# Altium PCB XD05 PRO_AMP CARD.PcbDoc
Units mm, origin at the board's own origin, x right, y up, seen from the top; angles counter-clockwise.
Board outline 39.9 x 32.4 mm, 4 copper layers (Top Layer, Signal Layer 1, Signal Layer 2, Bottom Layer), stack 1.58 mm thick; 39 components, 719 nets, 142 pads, 70 vias.
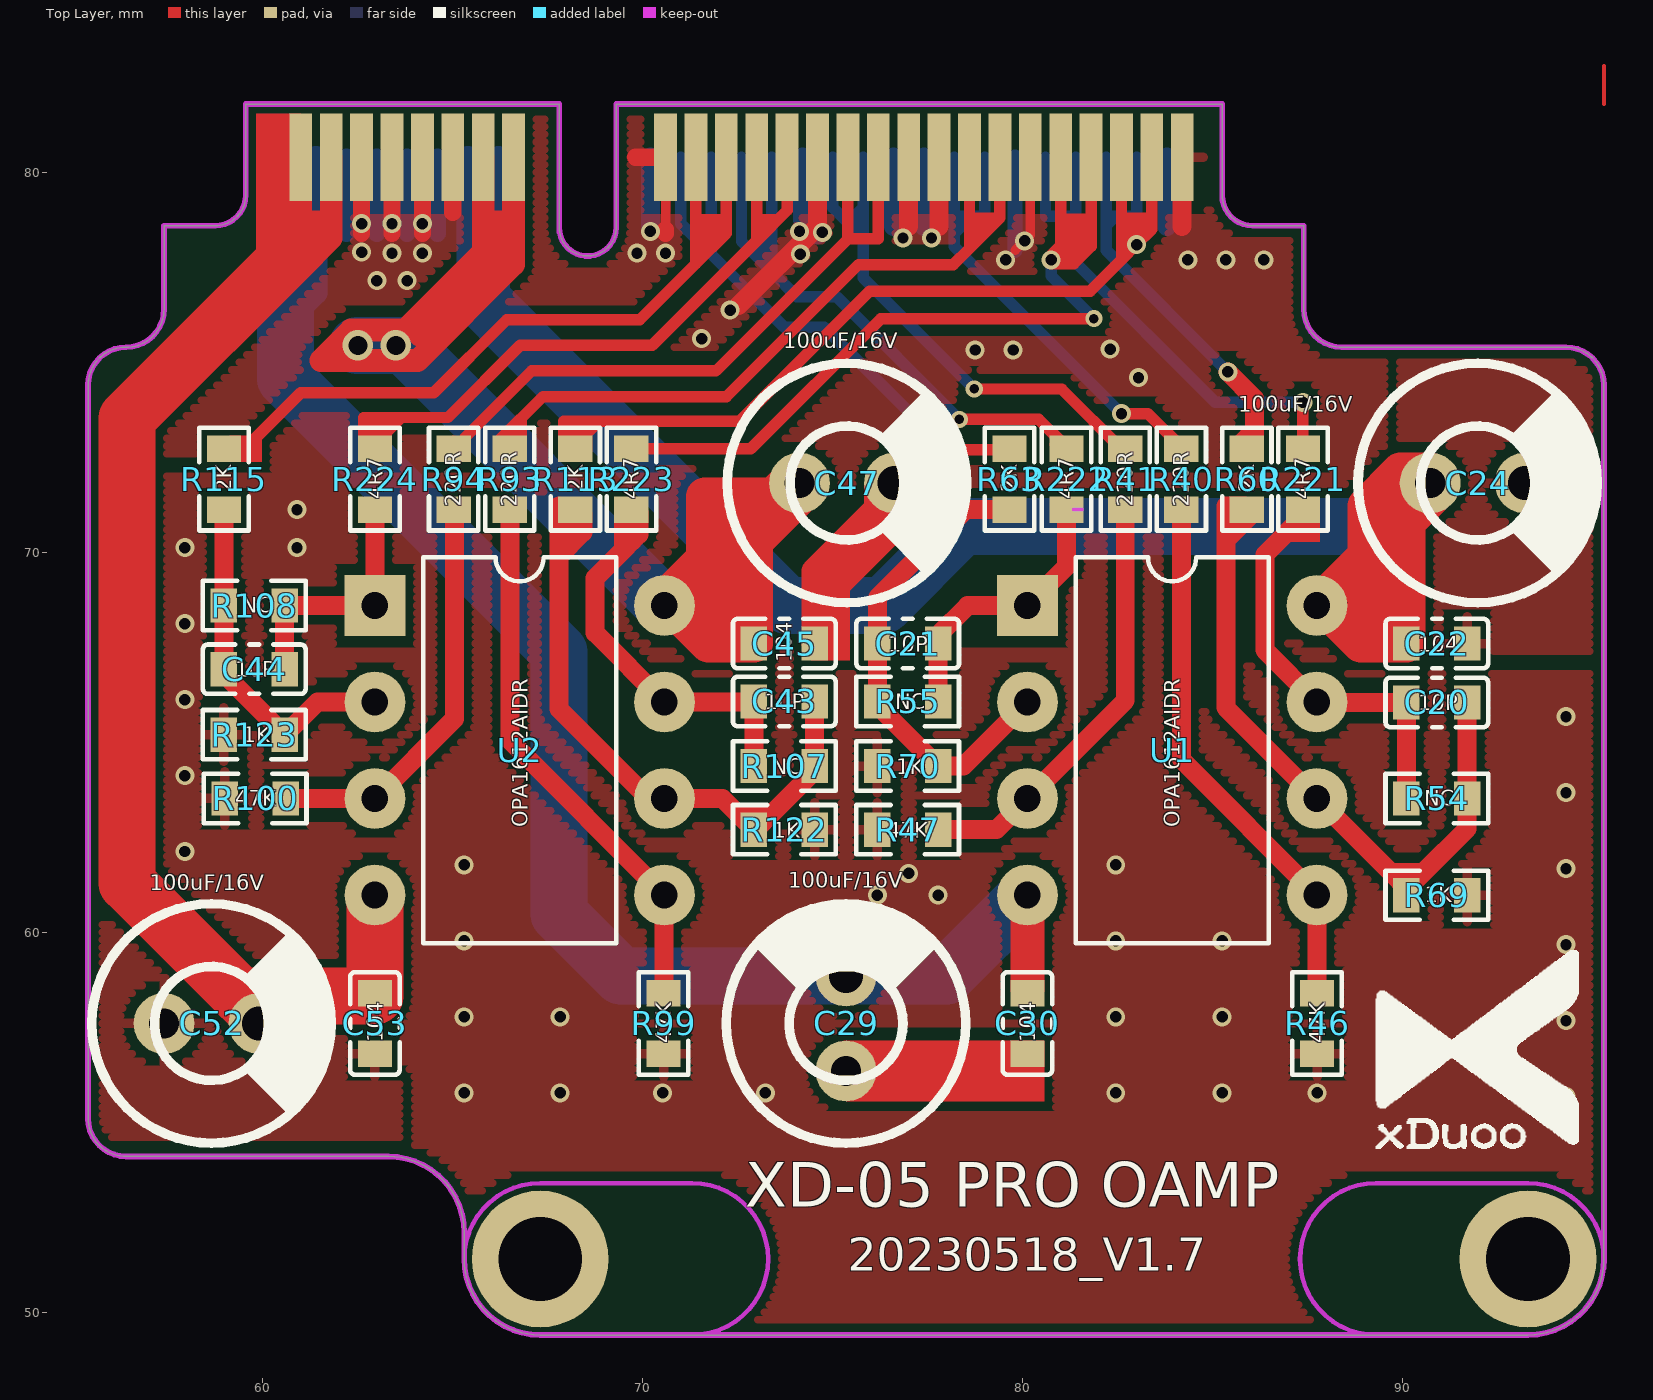
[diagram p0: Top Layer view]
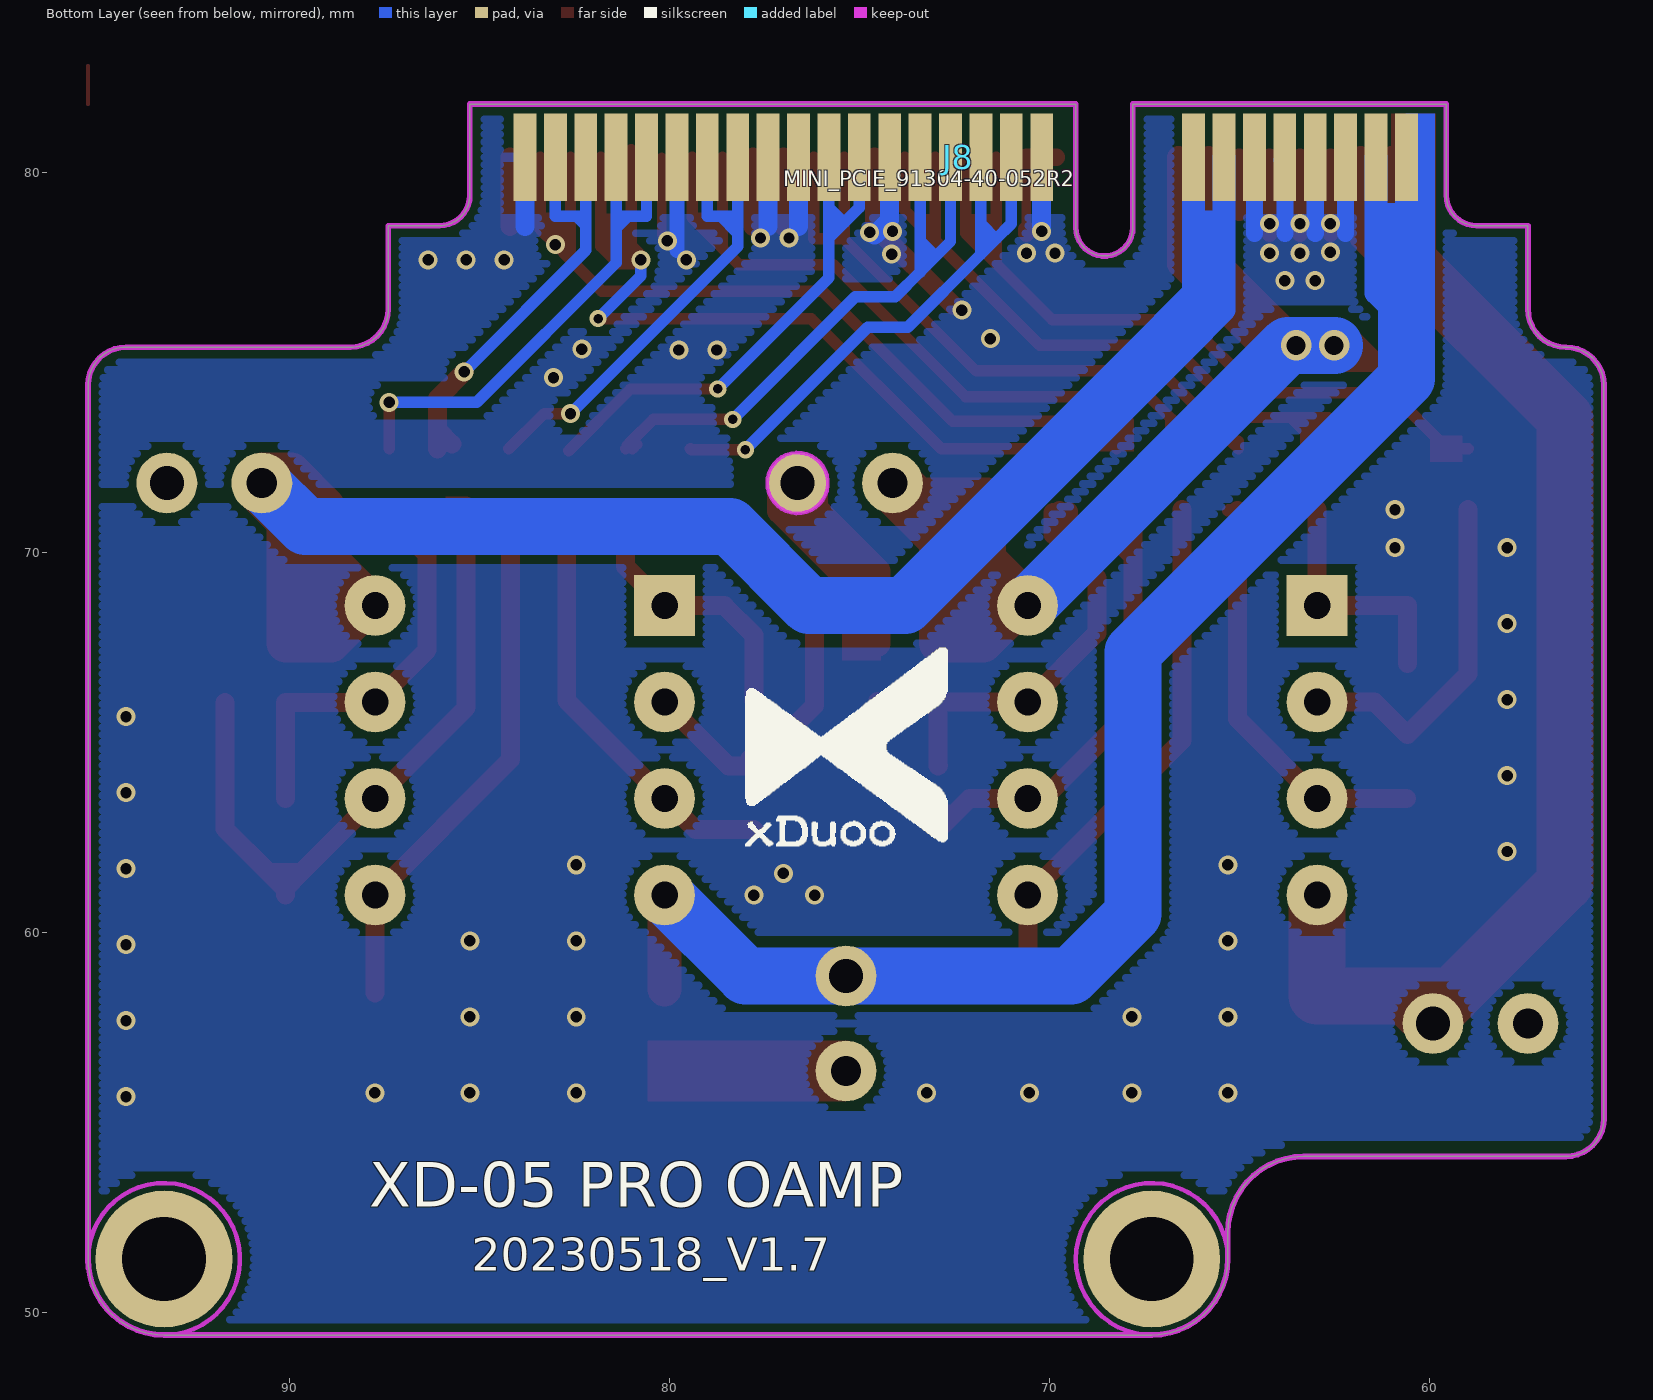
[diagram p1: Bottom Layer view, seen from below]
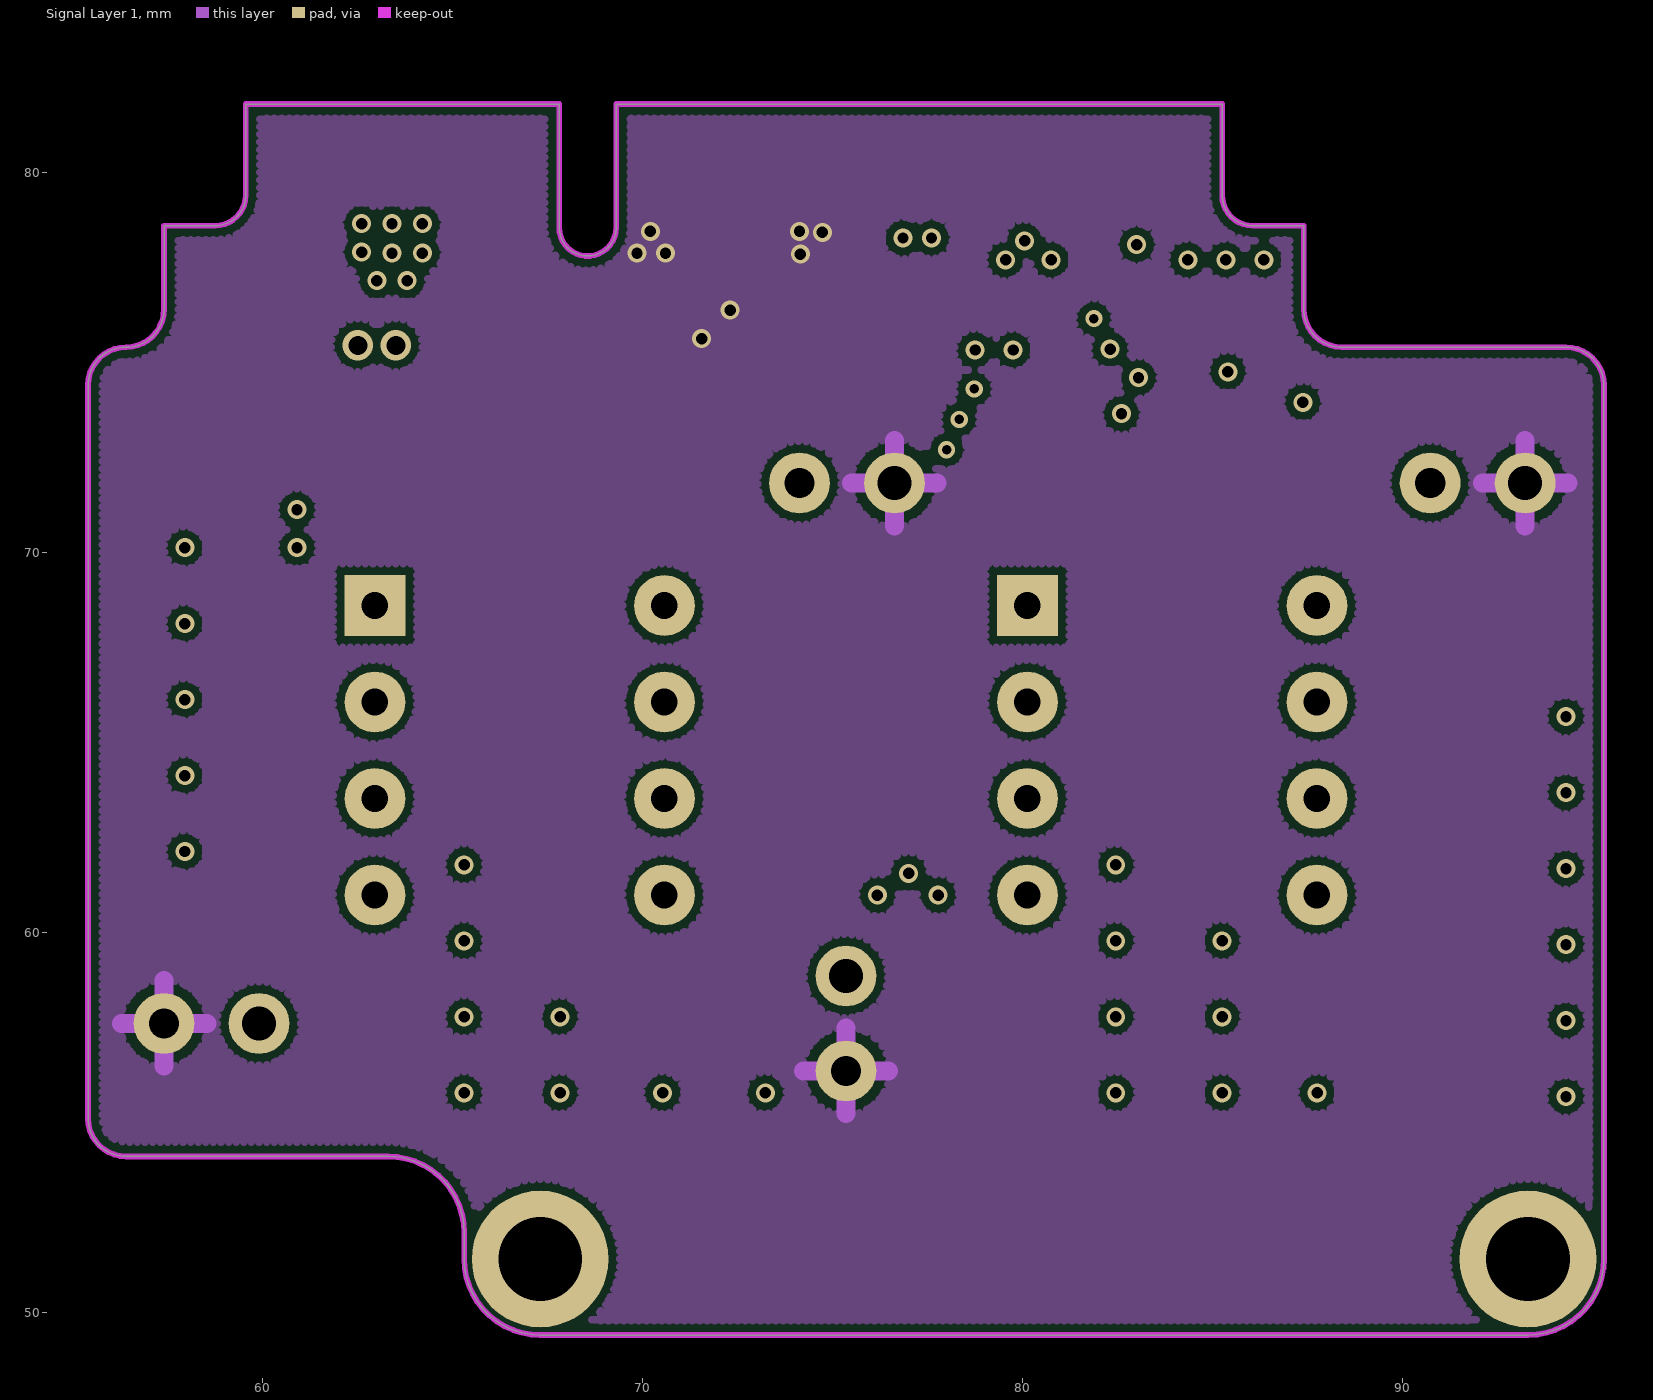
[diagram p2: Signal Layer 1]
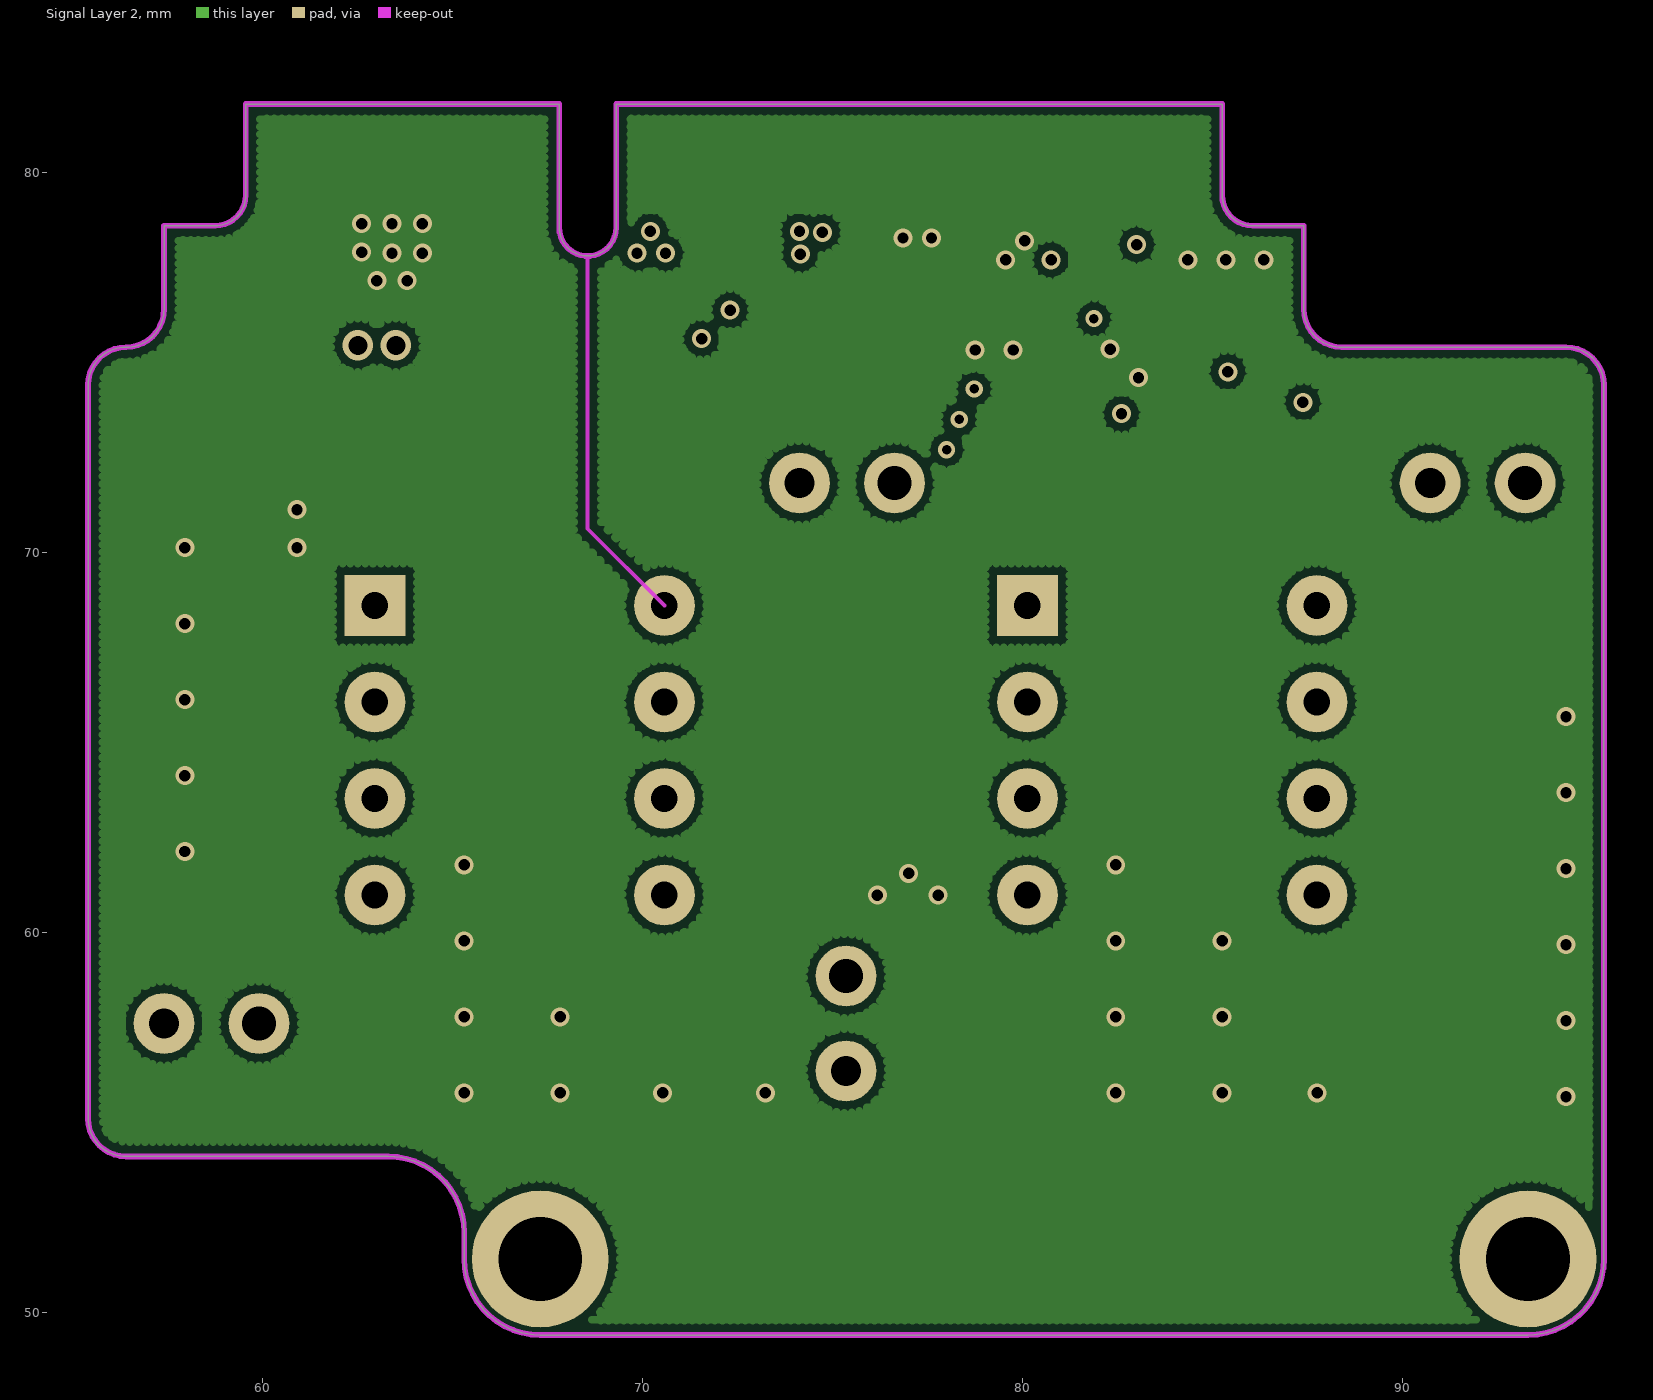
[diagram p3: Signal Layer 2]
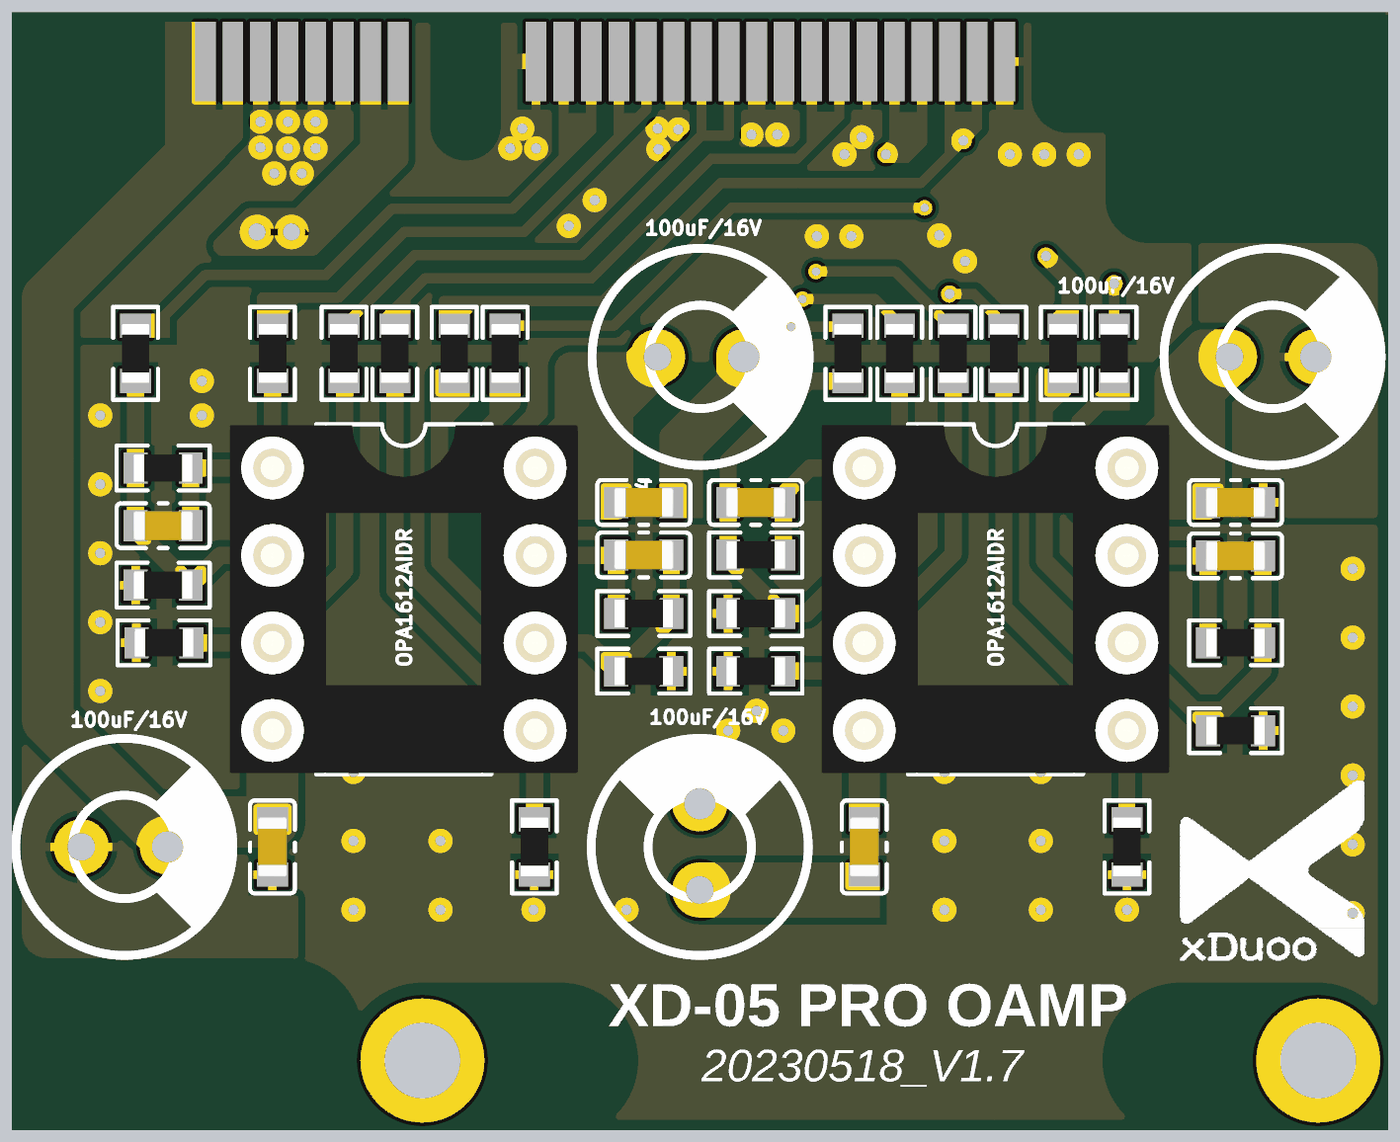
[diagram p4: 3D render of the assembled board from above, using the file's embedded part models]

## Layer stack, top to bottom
Top Solder: solder mask 0.01, Solder Resist, Dk 3.5
Top Layer: signal copper 0.035
Dielectric 1: core 0.48, FR-4, Dk 4.2
Signal Layer 1: signal copper 0.035
Dielectric 3: prepreg 0.48, Dk 4.2
Signal Layer 2: signal copper 0.035
Dielectric 2: core 0.48, Dk 4.2
Bottom Layer: signal copper 0.035
Bottom Solder: solder mask 0.01, Solder Resist, Dk 3.5

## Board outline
56.4,54.1 63.3,54.1 cw(c63.3,52.1) 65.3,52.1 65.3,51.4 ccw(c67.3,51.4) 67.3,49.4 93.3,49.4 ccw(c93.3,51.4) 95.3,51.4 95.3,74.4 ccw(c94.3,74.4) 94.3,75.4 88.4,75.4 cw(c88.4,76.4) 87.4,76.4 87.4,78.6 86.05,78.6 cw(c86.05,79.4) 85.25,79.4 85.25,81.8 69.3,81.8 69.3,78.55 cw(c68.55,78.55) 67.8,78.55 67.8,81.8 59.55,81.8 59.55,79.4 cw(c58.75,79.4) 58.75,78.6 57.4,78.6 57.4,76.4 cw(c56.4,76.4) 56.4,75.4 ccw(c56.4,74.4) 55.4,74.4 55.4,55.1 ccw(c56.4,55.1)

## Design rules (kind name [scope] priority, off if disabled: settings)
Clearance [All] p1: gap=0.2 ignorepadtopadclearanceinfootprint=FALSE except(0: Arc-Hole Track-Hole SMDPad-Hole THPad-Hole Via-Hole Fill-Hole Poly-Hole Region-Hole Text-Hole)
PlaneConnect [All] p1: planeconnectstyle=Relief reliefexpansion=0.508 reliefentries=4 reliefconductorwidth=0.25 reliefairgap=0.254
PolygonConnect PolygonConnect_1 [All vs IsVia] p1: connectstyle=Direct reliefconductorwidth=0.254 reliefentries=4 polygonreliefangle="90 Angle" airgapwidth=0.254
PolygonConnect [All] p2: connectstyle=Relief reliefconductorwidth=0.25 reliefentries=4 polygonreliefangle="90 Angle" airgapwidth=0.254
RoutingVias [All] p1: holewidth=0.25 width=0.45 viastyle="Through Hole" minholewidth=0.25 minwidth=0.45 maxholewidth=0.25 maxwidth=0.45
SolderMaskExpansion [All] p1: expansion=0.102
Width [All] p1: maxlimit=10 minlimit=0.15 preferedwidth=0.15
29 further rules are at their usual default settings.

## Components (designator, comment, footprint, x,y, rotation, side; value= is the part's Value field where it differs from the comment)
C20 "10P" C0603 91.7,66.05 r180 top
C21 "10P" C0603 76.175,67.6 r0 top
C22 "104" C0603 90.1,67.6 r0 top
C24 "100uF/16V" C6.5 90.725,71.825 r0 top
C29 "100uF/16V" C6.5 75.35,56.35 r90 top locked
C30 "104" C0603 80.125,58.4 r270 top
C43 "10P" C0603 74.525,66.075 r180 top
C44 "10P" C0603 58.975,66.925 r0 top
C45 "104" C0603 72.925,67.6 r0 top
C47 "100uF/16V" C6.5 74.125,71.825 r0 top
C52 "100uF/16V" C6.5 57.4,57.6 r0 top
C53 "104" C0603 62.95,58.4 r270 top
J8 "MINI_PCIE_91304-40-052R2" MINI_PCIE_91304-40-052R2_PCB 72.4,81.8 r0 bottom locked
R40 "220R" R0603 84.175,72.725 r270 top
R41 "220R" R0603 82.7,72.725 r270 top
R46 "47K" R0603 87.75,58.4 r270 top
R47 "47K" R0603 77.775,62.7 r180 top
R54 "NC" R0603 91.7,63.525 r180 top
R55 "NC" R0603 76.175,66.075 r0 top
R60 "2K" R0603 85.9,71.125 r90 top
R63 "2K" R0603 79.65,71.125 r90 top
R69 "1K" R0603 90.1,60.975 r0 top
R70 "1K" R0603 77.775,64.375 r180 top
R93 "220R" R0603 66.5,72.725 r270 top
R94 "220R" R0603 65.025,72.725 r270 top
R99 "47K" R0603 70.55,58.4 r270 top
R100 "47K" R0603 60.6,63.525 r180 top
R107 "NC" R0603 74.525,64.375 r180 top
R108 "NC" R0603 58.975,68.6 r0 top
R113 "2K" R0603 68.225,71.125 r90 top
R115 "2K" R0603 58.975,71.125 r90 top
R122 "1K" R0603 72.925,62.7 r0 top
R123 "1K" R0603 60.575,65.2 r180 top
R221 "4R7" R0603 87.375,71.125 r90 top
R222 "4R7" R0603 81.15,71.125 r90 top
R223 "4R7" R0603 69.7,71.125 r90 top
R224 "4R7" R0603 62.95,71.125 r90 top
U1 "OPA1612AIDR" DIP8 80.125,68.6 r0 top locked
U2 "OPA1612AIDR" DIP8 62.95,68.6 r0 top locked

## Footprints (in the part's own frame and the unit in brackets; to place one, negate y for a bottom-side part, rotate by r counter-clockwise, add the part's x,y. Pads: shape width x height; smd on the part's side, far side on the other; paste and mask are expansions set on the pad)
C6.5 [mm]
  round 1.6 hole 0.8: 1(0,0)
  round 1.6 hole 0.9: 2(2.5,0)
  silkscreen extent -1.9,-3.15 4.4,3.15, body extent -1.94,-3.2 4.44,3.2, height 2.5
C0603 [mm]
  rect 0.7x0.9 smd: 1(0,0) 2(1.6,0)
  silkscreen extent -0.55,-0.65 2.15,0.65, body extent -0.07,-0.44 1.68,0.44, height 0.92
DIP8 [mm]
  rect 1.6x1.6 hole 0.7: 1(0,0)
  round 1.6 hole 0.7: 2(0,-2.54) 3(0,-5.08) 4(0,-7.62) 5(7.62,-7.62) 6(7.62,-5.08) 7(7.62,-2.54) 8(7.62,0)
  silkscreen extent 1.27,-8.89 6.35,1.27, body extent -1.24,-8.86 8.86,1.24, height 4.6
MINI_PCIE_91304-40-052R2_PCB [mm]
  rect 0.6x2.3 smd: 1(-11.8,1.4) 3(-11,1.4) 5(-10.2,1.4) 7(-9.4,1.4) 9(-8.6,1.4) 11(-7.8,1.4) 13(-7,1.4) 15(-6.2,1.4) 17(-2.2,1.4) 19(-1.4,1.4) 21(-0.6,1.4) 23(0.2,1.4) 25(1,1.4) 27(1.8,1.4) 29(2.6,1.4) 31(3.4,1.4) 33(4.2,1.4) 35(5,1.4) 37(5.8,1.4) 39(6.6,1.4) 41(7.4,1.4) 43(8.2,1.4) 45(9,1.4) 47(9.8,1.4) 49(10.6,1.4) 51(11.4,1.4)
  rect 0.6x2.3 smd far side: 2(-11.4,1.4) 4(-10.6,1.4) 6(-9.8,1.4) 8(-9,1.4) 10(-8.2,1.4) 12(-7.4,1.4) 14(-6.6,1.4) 16(-5.8,1.4) 18(-1.8,1.4) 20(-1,1.4) 22(-0.2,1.4) 24(0.6,1.4) 26(1.4,1.4) 28(2.2,1.4) 30(3,1.4) 32(3.8,1.4) 34(4.6,1.4) 36(5.4,1.4) 38(6.2,1.4) 40(7,1.4) 42(7.8,1.4) 44(8.6,1.4) 46(9.4,1.4) 48(10.2,1.4) 50(11,1.4) 52(11.8,1.4)
  Keep-Out Layer lines w0.15: -15,3.2 -13.65,3.2 cw(c-13.65,2.4) -12.85,2.4 -12.85,0 -4.6,0 -4.6,3.25 cw(c-3.85,3.25) -3.1,3.25 -3.1,0 12.85,0 12.85,2.4 cw(c13.65,2.4) 13.65,3.2 15,3.2
R0603 [mm]
  rect 0.7x0.9 smd: 1(0,0) 2(1.6,0)
  silkscreen extent -0.55,-0.65 2.15,0.65, body extent -0.05,-0.4 1.65,0.4, height 0.55

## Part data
C20 C21 C22 C30 C43 C44 C45 C53: library part C
C24 C29 C47 C52: library part C+
R40 R41 R46 R47 R54 R55 R60 R63 R69 R70 R93 R94 R99 R100 R107 R108 R113 R115 R122 R123 R221 R222 R223 R224: library part R2
U1 U2: library part AMP

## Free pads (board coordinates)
  round 3.6 hole 2.2: 1(67.3,51.4) 1(93.3,51.4)

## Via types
v1: diameter 0.5, hole 0.3, Top Layer to Bottom Layer, 64 vias
v2: diameter 0.45, hole 0.25, Top Layer to Bottom Layer, 4 vias
v3: diameter 0.8, hole 0.5, Top Layer to Bottom Layer, 2 vias

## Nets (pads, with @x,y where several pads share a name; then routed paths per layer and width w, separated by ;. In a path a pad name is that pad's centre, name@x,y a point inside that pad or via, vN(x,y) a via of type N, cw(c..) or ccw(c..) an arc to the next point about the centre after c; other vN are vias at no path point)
3.5/4.4_SEL: 
3.5_EN: 
4.4_EN: 
4.4_IN_EN: 
4.4_L+: 
4.4_L-: 
4.4_LIN+: 
4.4_LIN-: 
4.4_LOUT+: 
4.4_LOUT-: 
4.4_OUT_EN: 
4.4_R+: 
4.4_R-: 
4.4_RIN+: 
4.4_RIN-: 
4.4_ROUT+: 
4.4_ROUT-: 
6.35/4.4_DET: 
+VCC: 
-VEE: 
A+8V: 
A+VCC: 
A-8V: 
A-VEE: 
AD_KEY1: 
AGND: J8.5 J8.6 J8.7 J8.8 J8.9 J8.10 J8.11 J8.12 J8.33 J8.34 J8.35 J8.36 J8.41 J8.42 J8.51 J8.52 R46.2 R47.2 R69.2 R70.2 R99.2 R100.2 R122.2 R123.2 | length 31.6
  Top Layer w0.25: 79.8,77.95 v1(80.05,78.2) 80.2,78.35 J8.42
  Top Layer w0.45: 62.6,78.4 J8.6 ; 63.4,78.4 J8.8 ; 64.2,78.4 v1(64.2,78.65) J8.10 ; 65,78.95 J8.12
  Top Layer w0.5: 77,78.575 J8.34 ; 77.8,78.575 J8.36 ; 84.2,78.575 J8.52
  Bottom Layer w0.4: 79.8,77.95 J8.41
  Bottom Layer w0.45: 62.2,78.4 J8.5 ; 63,78.4 J8.7 ; 63.8,78.4 J8.9 J8.9@63.875,80.325 ; 64.6,78.4 J8.11
  Bottom Layer w0.5: 76.6,78.575 J8.33 ; 77.4,78.575 J8.35 ; 83.8,78.575 J8.51
  other v1: 94.3,55.675 65.3,55.775 67.825,55.775 70.525,55.775 73.225,55.775 82.45,55.775 85.25,55.775 87.75,55.775 94.3,57.675 65.3,57.775 67.825,57.775 82.45,57.775 85.25,57.775 94.3,59.675 65.3,59.775 82.45,59.775 85.25,59.775 76.175,60.975 77.775,60.975 77,61.55 94.3,61.675 65.3,61.775 82.45,61.775 57.95,62.125 94.3,63.675 57.95,64.125 94.3,65.675 57.95,66.125 57.95,68.125 57.95,70.125 60.9,70.125 60.9,71.125 83.05,74.6 78.75,75.325 79.75,75.325 82.3,75.35 63,77.15 63.8,77.15 79.55,77.7 84.35,77.7 85.35,77.7 86.35,77.7 63.4,77.875 64.2,77.875 62.6,77.9 76.85,78.275 77.6,78.275 62.6,78.65 63.4,78.65
AGND_1: 
AGND_AP: C22.2 C24.2 C29.1 C30.2 C45.2 C47.2 C52.1 C53.2 J8.17 J8.18 J8.27 J8.28 | length 46.5
  Top Layer w0.25: 70.6,78.5 J8.18
  Top Layer w0.45: 69.811,80.4 J8.18 ; 70.6,78.4 70.6,78.5
  Top Layer w0.5: 72.525,76.5 74.6,78.575 J8.28 ; C47.2 C47.2@76.625,72.123
  Top Layer w0.7: C29.1@75.35,56.8 76.425,56.8 ; C29.1@75.775,56.15 76.425,56.8 ; C47.2 76.625,71.6 74.525,69.5 C45.2 75.1,67.6 75.1,69.125 77.075,71.1 C47.2@77.075,71.825 ; C30.2 76.425,56.8 ; C24.2@93.1,71.625 C24.2@93.1,71.825
  Signal Layer 1 w0.5: 56.275,57.6 C52.1 ; 57.4,58.725 C52.1 ; 57.4,56.475 C52.1 ; 58.525,57.6 C52.1 ; 74.225,56.35 C29.1 75.35,55.225 ; 75.35,57.475 C29.1 76.475,56.35 ; 75.5,71.825 C47.2 ; 76.625,70.7 C47.2 ; C47.2 77.75,71.825 ; 76.625,72.95 C47.2 ; 92.1,71.825 C24.2 ; 93.225,70.7 C24.2 ; C24.2 94.35,71.825 ; 93.225,72.95 C24.2
  Bottom Layer w0.5: v1@70.2,78.575 J8.17 ; J8.27 74.2,78.75 v1@74.6,78.35
  other v1: 71.55,75.625 72.3,76.375 74.15,77.85 69.85,77.875 70.6,77.875 74.725,78.425 70.2,78.45 74.125,78.45
AGND_L: 
AGND_LS: 
AGND_P: 
AGND_R: 
AGND_RS: 
AMP_L+: J8.37 J8.39 R40.1 | length 13.5
  Top Layer w0.3: v1(82.6,73.65) 83.3,73.65 R40.1@84.225,72.725
  Bottom Layer w0.3: J8.37 78.2,78.4 ; 78.225,78.85 78.65,78.85 ; J8.39 79,78.85 78.65,78.85 ; v1(82.6,73.65) 78.2,78.05 78.2,78.4 ; 78.2,78.4 78.65,78.85
AMP_L-: J8.29 J8.31 R41.1 | length 15.1
  Top Layer w0.3: v2(78.725,74.3) 81.025,74.3 R41.1@82.65,72.675
  Bottom Layer w0.3: J8.29 75,79.075 75.4,78.675 ; 75.625,78.625 75.625,78.775 ; J8.31 75.8,79.075 ; v2(78.725,74.3) 75.8,77.225 75.8,78.275 ; 75.4,78.675 75.8,78.275 ; 75.4,78.675 75.8,79.075 ; 75.8,78.275 75.8,79.075
AMP_PWR_EN: 
AMP_R+: J8.38 J8.40 R93.1 | length 20.8
  Top Layer w0.3: R93.1@66.225,72.95 67.375,74.1 72.205,74.1 75.68,77.575 78.175,77.575 78.6,78 ; J8.38 78.6,78 ; 78.625,78.8 79.4,78.8 ; 78.875,78.4 78.875,78.75 78.95,78.75 ; J8.40 79.4,78.8 ; 78.6,78 79.4,78.8
AMP_R-: J8.30 J8.32 R94.1 | length 17.8
  Top Layer w0.3: R94.1 R94.1@65.025,72.925 ; R94.1@65.125,72.825 67.075,74.775 71.925,74.775 75.4,78.25 J8.30 ; 75.4,78.25 76.2,78.25 J8.32
"AUDIO STREAM": 
AUX_L: 
AUX_L+: 
AUX_L-: 
AUX_LIN: 
AUX_LOUT: 
AUX_R: 
AUX_R+: 
AUX_R-: 
AUX_RIN: 
AUX_ROUT: 
AVCC_5V: 
BAT_DET: 
BD_SCL: 
BD_SDA: 
BOOST_A: 
BOOST_B: 
BOOT0: 
BT+3V3: 
BT_BCLK: 
BT_DATA: 
BT_DM: 
BT_DP: 
BT_LRCK: 
BT_MCLK: 
BT_OSC_SEL: 
BT_START: 
BT_UART_RX: 
BT_UART_TX: 
BT_VCC: 
C+3V3: 
CC1: 
CC2: 
CHG_DET: 
CHG_SW: 
CS_BCLK: 
CS_LRCK: 
CS_MCLK: 
CS_RST: 
CS_SDOUT: 
D+1V5: 
D+3V3: 
D+VCC: 
D-GND: 
DA+VCC: 
DA-VEE: 
DAC_L: 
DAC_L1+: 
DAC_L1-: 
DAC_L+: 
DAC_L-: 
DAC_LOUT: 
DAC_LOUT+: 
DAC_LOUT-: 
DAC_MCLK_SEL: 
DAC_PWR: 
DAC_PWR_EN: 
DAC_R: 
DAC_R1+: 
DAC_R1-: 
DAC_R+: 
DAC_R-: 
DAC_ROUT: 
DAC_ROUT+: 
DAC_ROUT-: 
DAC_RST: 
DAC_RST: 
DAC_SEL1: 
DAC_SEL2: 
DC_DET: 
DC_PWR_EN: 
DC_VCC: 
DGND: 
DIN: 
DM1: 
DM2: 
DM_IN: 
DOP_DET: 
DP1: 
DP2: 
DP_IN: 
DSD/PCM_MODE: 
DSD_CH: 
EXCLKI: 
EXCLKO: 
F+3V3: 
FS1: 
FS2: 
FS3: 
FS4: 
GW+1V2: 
GW+3V3: 
GW_SEL1: 
GW_SEL2: 
I2C_SCL: 
I2C_SDA: 
IBCLK: 
ILRCK: 
IOR3A: 
IOUT_LN: 
IOUT_LP: 
IOUT_RN: 
IOUT_RP: 
JTAG_TCK: 
JTAG_TDI: 
JTAG_TDO: 
JTAG_TMS: 
KEY: 
KEY_ON: 
L1+: 
L1-: 
L2+: 
L2-: 
L+: 
L+VCC: C22.1 C24.1 J8.13 J8.15 U1.8 | length 50.8
  Top Layer w1: C24.1@90.725,72.123 89.948,72.123 89.05,71.225 89.05,69.905 87.826,68.681 88.907,67.6 C22.1 90.1,70.8 C24.1@90.775,71.475
  Bottom Layer w0.6: J8.13 65.4,76.375 66.2,75.575 ; J8.15 66.2,76.85 67,76.05
  Bottom Layer w1.5: 66.225,76.175 73.8,68.6 76.325,68.6 78.4,70.675 89.575,70.675 C24.1
L-: 
L-VEE: C29.2 C30.1 J8.1 J8.3 U1.4 | length 43.8
  Top Layer w0.9: C30.1@80.125,58.5 U1.4@80.125,60.725
  Bottom Layer w0.6: 60.284,76.841 60.6,77.156 J8.1 ; 60.85,76.275 61.4,76.825 J8.3
  Bottom Layer w1.5: 60.6,77.156 60.6,74.573 67.8,67.373 67.8,60.475 69.425,58.85 C29.2 77.995,58.85 U1.4
L_CH: 
L_MUTE: 
L_VU_ADC: 
LI+: J8.43 J8.45 R221.2 | length 14.1
  Top Layer w0.3: R221.2 v1(87.375,73.95)
  Bottom Layer w0.3: J8.43 80.6,78.85 81.075,78.85 ; J8.45 81.4,78.85 ; 87.125,73.95 85.069,73.95 81.4,77.619 81.4,78.525 ; 81.075,78.85 81.4,78.85 ; 81.075,78.85 81.4,78.525 ; 81.4,78.525 81.4,78.85
LI-: J8.23 J8.25 R222.2 | length 17.7
  Top Layer w0.3: v2(78.331,73.5) 80.425,73.5 81,72.925 R222.2@81.113,72.812 ; R222.2@80.862,72.838 R222.2@80.975,72.725 ; R222.2@81.062,72.813 R222.2
  Bottom Layer w0.3: J8.23 72.6,78.181 73.4,77.381 ; 73,77.8 73.4,78.2 ; 73.225,77.7 73.225,77.9 ; 73.4,77.375 73.4,77.381 ; 73.4,78.9 73.4,78.25 ; J8.25 73.4,78.25 ; v2(78.331,73.5) 75.106,76.725 74.056,76.725 73.4,77.381 ; 73.4,77.381 73.4,78.2 ; 73.4,78.2 73.4,78.25 ; 73.4,78.2 73.4,78.25
LO+: J8.47 J8.49 R60.2 | length 12.5
  Top Layer w0.5: v1(85.4,74.75) 86.1,74.05 86.1,73.225 ; R60.2@85.725,72.85 86.1,73.225 ; R60.2@86.1,72.725 86.1,73.225
  Bottom Layer w0.3: J8.47 82.2,78.6 ; 82.225,78.85 82.45,78.85 ; J8.49 83,78.85 82.45,78.85 ; v1(85.4,74.75) 82.2,77.95 82.2,78.6 ; 82.2,78.6 82.45,78.85
LO-: J8.19 J8.21 R63.2 | length 16.3
  Top Layer w0.3: v2(78,72.7) 78.95,72.7 79.425,72.7 R63.2@79.45,72.725
  Bottom Layer w0.3: J8.19 71,78.65 71.4,78.25 ; 71.625,78.1 71.625,78.325 ; 71.8,78.9 71.8,78.65 ; J8.21 71.8,78.65 ; v2(78,72.7) 74.775,75.925 73.725,75.925 71.8,77.85 ; 71.4,78.25 71.8,78.65 ; 71.4,78.25 71.8,77.85 ; 71.8,77.85 71.8,78.65
M+3V3: 
MCLK: 
MCLK_1/2_SELA: 
MCLK_1/2_SELB: 
MCLK_SEL: 
MCLK_XCORE: 
MIC-AP: 
MIC-BIAS: 
MQA_LED: 
MUTE: 
MUTE_L: 
MUTE_R: 
MUTEING: 
MUTING: 
NetC1_2: 
NetC2_1: 
NetC3_1: 
NetC4_2: 
NetC5_1: 
NetC6_1: 
NetC7_2: 
NetC8_1: 
NetC9_2: 
NetC10_1: 
NetC11_1: 
NetC11_2: 
NetC16_1: 
NetC16_2: 
NetC17_1: 
NetC17_2: 
NetC18_1: 
NetC18_2: 
NetC20_1: C20.1 R54.1 R60.1 R69.1 U1.6 | length 19.6
  Top Layer w0.5: 85.35,71.225 85.35,70.325 ; R60.1@86.05,71.025 85.35,70.325 ; R69.1 90.1,61.165 89.69,61.575 ; R69.1@90.15,61.175 90.55,61.575 ; C20.1 91.7,62.725 90.55,61.575 ; 85.35,70.325 85.35,65.915 89.69,61.575 ; 89.69,61.575 90.55,61.575
NetC20_2: C20.2 R54.2 R221.1 U1.7 | length 11.2
  Top Layer w0.5: U1.7@87.51,66.05 C20.2 R54.2 ; R221.1@87.51,71.075 86.375,69.94 86.375,67.43 U1.7
NetC21_1: C21.1 R55.1 R63.1 R70.1 U1.2 | length 12.9
  Top Layer w0.35: U1.2@80.37,66.05 U1.2@80.38,66.06
  Top Layer w0.5: R70.1@77.875,64.575 77.775,64.475 R70.1 ; R63.1@79.7,71.125 78.5,71.125 76.175,68.8 C21.1 R55.1 76.175,65.975 R70.1 ; U1.2@80.11,66.075 U1.2 78.44,64.375 R70.1
NetC21_2: C21.2 R55.2 R222.1 U1.1 | length 6.9
  Top Layer w0.5: R55.2 C21.2 77.775,67.825 78.55,68.6 U1.1@79.675,68.6 ; U1.1 81.15,69.625 R222.1
NetC25_1: 
NetC25_2: 
NetC26_1: 
NetC27_1: 
NetC27_2: 
NetC28_1: 
NetC34_1: 
NetC34_2: 
NetC39_1: 
NetC39_2: 
NetC40_1: 
NetC40_2: 
NetC41_1: 
NetC41_2: 
NetC43_1: C43.1 R107.1 R113.1 R122.1 U2.6 | length 18.3
  Top Layer w0.5: R113.1@67.8,71.225 67.8,69.9 ; 68.125,70.4 R113.1@68.125,70.875 ; R113.1@68.425,71 68.425,70.525 67.8,69.9 ; R122.1 72.515,63.11 ; R122.1@73.1,62.825 73.385,63.11 ; C43.1 74.525,64.25 73.385,63.11 ; 67.8,69.9 67.8,65.875 70.155,63.52 U2.6 72.105,63.52 72.515,63.11 ; 72.515,63.11 73.385,63.11
NetC43_2: C43.2 R107.2 R223.1 U2.7 | length 12.1
  Top Layer w0.3: U2.7 U2.7@70.96,66.06
  Top Layer w0.5: R223.1@69.5,71.075 69.5,70.075 ; R223.1@69.725,71.1 69.725,70.3 ; R223.1@69.9,71.05 69.9,70.475 69.725,70.3 ; U2.7 68.75,67.88 68.75,69.325 69.5,70.075 ; U2.7@70.96,66.06 72.91,66.06 C43.2 R107.2 R107.2@72.91,64.39 ; 69.5,70.075 69.725,70.3
NetC44_1: C44.1 R108.1 R115.1 R123.1 U2.2 | length 9.3
  Top Layer w0.5: R115.1 R108.1 58.975,66.8 R123.1 61.435,66.06 U2.2
NetC44_2: C44.2 R108.2 R224.1 U2.1 | length 6.4
  Top Layer w0.5: C44.2@60.575,67.075 R108.2 U2.1 R224.1
NetC48_1: 
NetC48_2: 
NetC49_1: 
NetC50_1: 
NetC50_2: 
NetC51_1: 
NetC58_1: 
NetC58_2: 
NetC59_2: 
NetC60_1: 
NetC60_2: 
NetC63_2: 
NetC65_2: 
NetC66_1: 
NetC67_2: 
NetC77_1: 
NetC77_2: 
NetC78_2: 
NetC79_1: 
NetC79_2: 
NetC82_2: 
NetC84_2: 
NetC85_2: 
NetC86_2: 
NetC95_1: 
NetC96_1: 
NetC101_1: 
NetC102_1: 
NetC105_2: 
NetC106_2: 
NetC107_1: 
NetC107_2: 
NetC110_1: 
NetC111_1: 
NetC115_1: 
NetC118_2: 
NetC120_1: 
NetC122_1: 
NetC123_1: 
NetC124_1: 
NetC126_2: 
NetC127_1: 
NetC128_1: 
NetC129_2: 
NetC130_1: 
NetC135_2: 
NetC136_2: 
NetC137_2: 
NetC138_1: 
NetC138_2: 
NetC144_1: 
NetC151_2: 
NetC163_2: 
NetC173_2: 
NetC175_1: 
NetC182_1: 
NetC193_1: 
NetC194_1: 
NetC195_1: 
NetC197_1: 
NetC197_2: 
NetC198_1: 
NetC208_2: 
NetC212_1: 
NetC213_1: 
NetC215_1: 
NetC218_2: 
NetC221_1: 
NetC224_2: 
NetC226_2: 
NetC232_2: 
NetC245_1: 
NetC247_2: 
NetC263_1: 
NetC263_2: 
NetC264_2: 
NetC266_1: 
NetC268_2: 
NetC269_2: 
NetC270_1: 
NetC273_1: 
NetC276_1: 
NetC276_2: 
NetC277_1: 
NetC278_1: 
NetC282_1: 
NetC282_2: 
NetC284_1: 
NetC285_2: 
NetC287_2: 
NetC288_2: 
NetC289_1: 
NetC292_1: 
NetC296_1: 
NetC297_1: 
NetC297_2: 
NetC298_2: 
NetC299_2: 
NetC306_1: 
NetC310_1: 
NetC311_1: 
NetC318_1: 
NetC319_1: 
NetC319_2: 
NetC326_1: 
NetC326_2: 
NetC329_2: 
NetC330_1: 
NetC331_1: 
NetC332_2: 
NetC333_1: 
NetC335_1: 
NetC336_1: 
NetC336_2: 
NetC337_1: 
NetC337_2: 
NetC338_2: 
NetC340_1: 
NetC341_1: 
NetC342_1: 
NetC343_1: 
NetC344_1: 
NetC345_1: 
NetC347_1: 
NetC350_1: 
NetC357_1: 
NetC367_2: 
NetC379_1: 
NetC392_1: 
NetC393_1: 
NetC402_1: 
NetC402_2: 
NetC408_2: 
NetC409_2: 
NetC410_2: 
NetC411_2: 
NetC412_2: 
NetC413_2: 
NetC414_2: 
NetC415_2: 
NetC416_1: 
NetC417_1: 
NetC418_1: 
NetC419_1: 
NetC420_2: 
NetC421_2: 
NetC422_2: 
NetC423_2: 
NetD1_2: 
NetD4_2: 
NetD11_1: 
NetD12_2: 
NetD13_1: 
NetD13_2: 
NetD14_1: 
NetD14_2: 
NetD15_1: 
NetD15_2: 
NetD16_1: 
NetD16_2: 
NetD17_1: 
NetD17_2: 
NetD19_1: 
NetD20_2: 
NetD21_1: 
NetD21_2: 
NetD22_1: 
NetD22_2: 
NetD23_1: 
NetD23_2: 
NetD24_1: 
NetD24_2: 
NetD25_1: 
NetD25_2: 
NetD27_1: 
NetD28_2: 
NetD28_4: 
NetD33_3: 
NetD43_1: 
NetD43_3: 
NetD47_2: 
NetD48_1: 
NetD49_1: 
NetD50_1: 
NetD51_1: 
NetD52_1: 
NetD53_1: 
NetD62_1: 
NetD62_2: 
NetD62_4: 
NetD63_1: 
NetD63_2: 
NetD63_4: 
NetD70_2: 
NetDV3_1: 
NetDV3_2: 
NetFB3_1: 
NetJ1_3: 
NetJ1_5: 
NetJ2_6: 
NetJ2_8: 
NetJK1_6: 
NetK1_16: 
NetL2_2: 
NetL4_1: 
NetL8_1: 
NetL8_2: 
NetMK2_A5: 
NetMK2_B5: 
NetP3_2: 
NetP3_3: 
NetP3_4: 
NetP3_5: 
NetP4_2: 
NetP4_3: 
NetP5_7: 
NetQ1_2: 
NetQ2_2: 
NetQ3_2: 
NetQ4_2: 
NetQ5_2: 
NetQ5_3: 
NetQ5_5: 
NetQ6_2: 
NetQ6_3: 
NetQ6_5: 
NetQ9_1: 
NetQ11_1: 
NetQ15_2: 
NetQ15_5: 
NetQ16_2: 
NetQ16_5: 
NetQ17_2: 
NetQ17_3: 
NetQ17_5: 
NetQ18_2: 
NetQ18_3: 
NetQ18_5: 
NetQ21_1: 
NetQ23_1: 
NetQ27_2: 
NetQ27_5: 
NetQ28_2: 
NetQ28_5: 
NetQ29_2: 
NetQ30_2: 
NetQ31_2: 
NetQ32_2: 
NetQ32_3: 
NetQ33_3: 
NetQ34_1: 
NetQ36_1: 
NetQ40_1: 
NetQ42_1: 
NetQ42_3: 
NetQ43_1: 
NetQ43_3: 
NetQ44_1: 
NetQ44_3: 
NetQ45_1: 
NetQ45_3: 
NetQ50_1: 
NetQ59_1: 
NetQ59_3: 
NetQ60_1: 
NetQ60_3: 
NetQ62_1: 
NetQ62_2: 
NetQ77_1: 
NetQ78_2: 
NetQ79_1: 
NetR12_1: 
NetR12_2: 
NetR16_2: 
NetR17_2: 
NetR22_1: 
NetR22_2: 
NetR33_1: 
NetR40_2: R40.2 R46.1 U1.5 | length 14.2
  Top Layer w0.5: R40.2 84.175,64.55 U1.5 87.745,58.405 R46.1
NetR41_2: R41.2 R47.1 U1.3 | length 11.4
  Top Layer w0.5: R47.1 79.305,62.7 82.7,66.095 R41.2
NetR62_2: 
NetR86_1: 
NetR93_2: R93.2 R99.1 U2.5 | length 14.4
  Top Layer w0.5: R93.2 66.5,65.05 U2.5 U2.5@70.575,60.975 ; R99.1 70.56,58.41 U2.5@70.56,60.97
NetR94_2: R94.2 R100.1 U2.3 | length 10.8
  Top Layer w0.3: R94.2@65.275,71.125 65.294,71.106 R94.2@65.3,71.1
  Top Layer w0.5: R100.1 62.945,63.525 U2.3 65.044,65.614 R94.2@65.044,71.106
NetR117_2: 
NetR133_2: 
NetR135_1: 
NetR135_2: 
NetR136_2: 
NetR137_2: 
NetR138_1: 
NetR140_1: 
NetR141_2: 
NetR143_1: 
NetR143_2: 
NetR144_2: 
NetR145_2: 
NetR146_1: 
NetR148_2: 
NetR150_2: 
NetR151_1: 
NetR168_1: 
NetR196_2: 
NetR199_1: 
NetR204_1: 
NetR205_1: 
NetR206_2: 
NetR207_2: 
NetR208_2: 
NetR211_2: 
NetR214_2: 
NetR225_1: 
NetR226_2: 
NetR227_2: 
NetR229_2: 
NetR230_2: 
NetR232_1: 
NetR234_2: 
NetR235_2: 
NetR236_2: 
NetR237_2: 
NetR238_2: 
NetR239_2: 
NetR240_2: 
NetR243_1: 
NetR244_1: 
NetR245_1: 
NetR246_1: 
NetR249_2: 
NetR251_1: 
NetR252_1: 
NetR253_1: 
NetR255_1: 
NetR258_2: 
NetR260_2: 
NetR263_2: 
NetR264_1: 
NetR265_1: 
NetR266_1: 
NetR267_2: 
NetR268_2: 
NetR270_2: 
NetR271_2: 
NetR282_1: 
NetR283_1: 
NetR286_1: 
NetR287_2: 
NetR295_1: 
NetR296_2: 
NetR298_1: 
NetR300_2: 
NetR305_2: 
NetR314_1: 
NetR316_2: 
NetR317_2: 
NetR327_1: 
NetR328_2: 
NetR330_2: 
NetR335_2: 
NetR344_1: 
NetR347_2: 
NetR349_1: 
NetR350_1: 
NetR351_1: 
NetR351_2: 
NetR357_1: 
NetR359_2: 
NetR361_2: 
NetR362_2: 
NetR366_2: 
NetR369_1: 
NetR377_2: 
NetR378_1: 
NetR388_2: 
NetR389_2: 
NetR413_1: 
NetR414_2: 
NetR417_1: 
NetR419_1: 
NetR420_1: 
NetR421_1: 
NetR422_1: 
NetR423_1: 
NetR425_2: 
NetR426_2: 
NetR431_2: 
NetR432_2: 
NetR433_2: 
NetR453_1: 
NetR453_2: 
NetR454_1: 
NetR455_1: 
NetR455_2: 
NetR457_1: 
NetR458_2: 
NetR460_1: 
NetR460_2: 
NetR461_2: 
NetR462_1: 
NetR462_2: 
NTC: 
OBCLK: 
ODATA: 
OLED1_/CS: 
OLED1_D/C: 
OLED1_SCL: 
OLED1_SI: 
OLED2_/CS: 
OLED2_D/C: 
OLED/PGA_SCL: 
OLED/PGA_SI: 
OLED_RST: 
OLRCK: 
OMCLK: 
OSC1: 
OSC2: 
OSC3: 
P+5V: 
P-5V: 
PGA_/CS: 
PH_L+: 
PH_L-: 
PH_LOUT+: 
PH_LOUT-: 
PH_R+: 
PH_R-: 
PH_ROUT+: 
PH_ROUT-: 
PRO_DET: 
PWR_EN: 
QC_DET: 
R1+: 
R1-: 
R2+: 
R2-: 
R+: 
R+VCC: C45.1 C47.1 J8.14 J8.16 U2.8 | length 43.5
  Top Layer w0.6: 64.15,75.7 66,77.55 ; J8.14 65.8,77.9 63.75,75.85 62.325,75.85 61.525,75.05 64.075,75.05 66.6,77.575 J8.16
  Top Layer w1: U2.8 70.57,68.762 71.636,69.829 71.636,71.466 73.436,71.466 73.68,71.71 74.01,71.71 C47.1 ; U2.8@70.732,68.6 71.732,67.6 C45.1 72.925,70.287 C47.1@74.238,71.6
  Bottom Layer w1.5: v3@62.489,75.45 v3(62.5,75.45) v3(63.5,75.45) 63.72,75.45 U2.8
R-: 
R-VEE: C52.2 C53.1 J8.2 J8.4 U2.4 | length 38.3
  Top Layer w0.5: 60.325,78.125 61,78.8 ; 60.375,77.725 61,78.35 61,78.1
  Top Layer w0.6: 61,78.8 J8.2 ; 61.05,77.525 61.8,78.275 J8.4
  Top Layer w1.5: 59.411,58.325 C52.2@59.886,57.85 ; C52.2@59.888,57.837 60.375,58.325 ; C52.2 59.9,57.627 60.375,58.102 60.375,58.325 ; 61,78.1 56.425,73.525 56.425,61.3 59.4,58.325 60.375,58.325 ; U2.4 C53.1 62.95,58.325 60.375,58.325
R_CH: 
R_MUTE: 
R_VU_ADC: 
RI+: J8.44 J8.46 R223.2 | length 22.3
  Top Layer w0.3: R223.2@69.7,72.875 R223.2 72.845,72.725 76.27,76.15 v2(81.875,76.15) ; v1@80.7,77.775 81,78.075 J8.44 J8.44@81,80.6 ; v1@80.75,77.6 81.35,77.6 81.8,78.05 J8.46
  Bottom Layer w0.3: v1(80.75,77.7) 80.75,77.275 v2(81.875,76.15)
RI-: J8.24 J8.26 R224.2 | length 18.1
  Top Layer w0.3: 62.65,73.55 63.65,73.55 ; R224.2 62.95,72.85 63.65,73.55 ; J8.24 73,78.2 ; J8.26 73.8,79 73,78.2 ; 63.65,73.55 64.875,73.55 66.775,75.45 70.25,75.45 73,78.2
RO+: J8.48 J8.50 R113.2 | length 23.7
  Top Layer w0.3: 67.925,73.45 68.85,73.45 ; R113.2 68.225,72.825 68.85,73.45 ; J8.48 82.6,78.5 ; J8.50 83.4,78.5 v1(83,78.1) ; 68.85,73.45 72.545,73.45 75.97,76.875 81.775,76.875 82.6,77.7 ; 82.6,77.7 82.6,78.5 ; 82.6,77.7 v1(83,78.1) ; 82.6,78.5 v1(83,78.1)
RO-: J8.20 J8.22 R115.2 | length 20.4
  Top Layer w0.3: R115.2 59.525,72.725 61,74.2 64.5,74.2 66.425,76.125 69.925,76.125 71.4,77.6 ; J8.20 71.4,77.6 ; J8.22 72.2,78.4 71.4,77.6
RST: 
RX0: 
RX1: 
RXN0: 
RXP0: 
S+5V: 
SCL: 
SDA: 
SEL_A: 
SEL_C: 
SPDIF_OUT: 
TCK: 
TDI: 
TDO: 
TMS: 
U_DATA/DSDL: 
U_LRCK/DSDR: 
U_MCLK_SEL: 
U_SCLK/DSD_BCK: 
USART0_RX: 
USART0_TX: 
USB_DM: 
USB_DP: 
USB_LINK: 
USB_MUTE: 
USB_PWR_EN: 
USB_UART_RX: 
USB_UART_TX: 
USB_VBUS_SET: 
V-GND: 
VBAT: 
VBAT_PWR_EN: 
VBUS1: 
VBUS2: 
VCC: 
VCC1: 
VCC2: 
VD1+: 
VD2+: 
VDD: 
VDD18: 
VDD33: 
VIN: 
VPP: 
VR_A: 
VR_B: 
XIN: 
XM_QSPI_D0: 
XM_QSPI_D1: 
XM_QSPI_D2: 
XM_QSPI_D3: 
XM_SPI_CS_N: 
XM_SPI_SCK: 
XMOS_NRST: 
XOUT: 
XTAL1: 
XTAL2: 
copper on no net: | length 1
  Top Layer w0.1: 95.3,81.8 95.3,82.8

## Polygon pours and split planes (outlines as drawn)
no net on Top Layer "Top Layer-No Net 5" (hatched Horizontal grid 0.2 track 0.2, remove dead copper, pour order 847): -77.825,353.5
AGND_1 on Top Layer "Top Layer-AGND_A 2" (hatched Horizontal grid 0.2 track 0.2, remove dead copper, pour order 819): -70.3,334.925
AGND_1 on Top Layer "Top Layer-AGND_A 3" (hatched Horizontal grid 0.2 track 0.2, remove dead copper, pour order 817): -70.3,334.925
AGND_1 on Top Layer "Top Layer-AGND_A 4" (hatched Horizontal grid 0.2 track 0.2, remove dead copper, pour order 815): -68.65,334.925
no net on Top Layer "Top Layer-No Net 6" (hatched Horizontal grid 0.2 track 0.2, remove dead copper, pour order 811): -68.65,334.925
no net on Top Layer "Top Layer-No Net 3" (hatched Horizontal grid 0.2 track 0.2, remove dead copper, pour order 797): -77.525,344.825
no net on Top Layer "Top Layer-No Net 4" (hatched Horizontal grid 0.2 track 0.2, remove dead copper, pour order 795): -77.55,353.5
AGND on Top Layer "Top Layer-AGND 5" (hatched Horizontal grid 0.2 track 0.2, remove dead copper, pour order 709): 55.4,72.075 59.8,72.075 59.8,73 61.075,74.275 73.436,74.275 73.436,67.55 79,67.55 79,71.125 95.3,71.125 95.3,49.4 55.4,49.4
AGND_AP on Top Layer "Top Layer-AGND_AP 1" (hatched Horizontal grid 0.2 track 0.2, remove dead copper, pour order 695): 55.4,61.3 56.425,61.3 59.325,58.4 63.6,58.4 63.6,54.1 55.4,54.1
AGND on Top Layer "Top Layer-AGND 3" (hatched Horizontal grid 0.2 track 0.2, remove dead copper, pour order 711): 67.8,81.8 67.8,77.475 64.6,74.275 61.075,74.275 59.275,72.475 55.4,72.475 55.4,81.8
AGND on Top Layer "Top Layer-AGND 2" (hatched Horizontal grid 0.2 track 0.2, remove dead copper, pour order 705): 95.3,71.775 95.3,81.8 73.725,81.8 73.725,71.775
AGND_AP on Top Layer "Top Layer-AGND_AP 2" (hatched Horizontal grid 0.2 track 0.2, remove dead copper, pour order 787): 95.3,67.25 95.3,75.4 89.925,75.4 89.925,67.25
AGND_AP on Top Layer "Top Layer-AGND_AP" (hatched Horizontal grid 0.2 track 0.2, remove dead copper, pour order 697): 65.8,81.8 75.4,81.8 75.4,78.25 71.925,74.775 65.8,74.775
no net on Top Layer "Top Layer-No Net" (hatched Horizontal grid 0.2 track 0.2, remove dead copper, pour order 629): -38.55,353.5
AVCC_5V on Top Layer "Top Layer-AVCC_5V 2" (hatched Horizontal grid 0.2 track 0.2, remove dead copper, pour order 601): -68.825,341.3
AGND on Top Layer "Top Layer-AGND 12" (hatched Horizontal grid 0.2 track 0.2, remove dead copper, pour order 585): -77.1,353.5
no net on Top Layer "Top Layer-AGND_R 3" (hatched Horizontal grid 0.2 track 0.2, remove dead copper, pour order 551): -76.55,328.525
no net on Top Layer "Top Layer-AGND_P 5" (hatched Horizontal grid 0.2 track 0.2, remove dead copper, pour order 535): -61.05,325.65
no net on Top Layer "Top Layer-AGND_P 1" (hatched Horizontal grid 0.2 track 0.2, remove dead copper, pour order 473): -37.225,331.6
no net on Top Layer "Top Layer-AGND_L 1" (hatched Horizontal grid 0.2 track 0.2, remove dead copper, pour order 441): -62,338.125
no net on Bottom Layer "Bottom Layer-No Net 8" (hatched Horizontal grid 0.2 track 0.2, remove dead copper, pour order 839): -32.925,353.5
AGND on Bottom Layer "Bottom Layer-AGND 4" (hatched Horizontal grid 0.2 track 0.2, remove dead copper, pour order 719): 55.4,78.6 61.4,78.6 61.4,75.675 63.5,75.675 63.5,75.67 70.57,68.6 71.885,69.915 72.485,69.915 73.8,68.6 76.325,68.6 79.05,71.325 95.3,71.325 95.3,49.4 55.4,49.4
AGND on Bottom Layer "Bottom Layer-AGND 10" (hatched Horizontal grid 0.2 track 0.2, remove dead copper, pour order 715): 61.4,81.8 61.4,75.675 63.5,75.675 63.5,75.67 70.57,68.6 70.57,71.83 66.2,76.2 66.2,81.8
AGND_AP on Bottom Layer "Bottom Layer-AGND_AP" (hatched Horizontal grid 0.2 track 0.2, remove dead copper, pour order 701): 66.2,81.8 75.8,81.8 75.8,74.9 78,72.7 78,70.275 76.325,68.6 73.975,68.6 66.2,76.375
AGND on Bottom Layer "Bottom Layer-AGND 11" (hatched Horizontal grid 0.2 track 0.2, remove dead copper, pour order 703): 95.3,71.725 78.4,71.725 78.4,72.3 75.8,74.9 75.8,81.8 95.3,81.8
AGND on Bottom Layer "Bottom Layer-AGND 9" (hatched Horizontal grid 0.2 track 0.2, remove dead copper, pour order 717): 55.4,74.2
no net on Bottom Layer "Bottom Layer-No Net 4" (hatched Horizontal grid 0.2 track 0.2, remove dead copper, pour order 691): 74.85,140.1
no net on Bottom Layer "Bottom Layer-No Net 2" (hatched Horizontal grid 0.2 track 0.2, remove dead copper, pour order 625): -56.525,352.8
no net on Bottom Layer "Bottom Layer-No Net 3" (hatched Horizontal grid 0.2 track 0.2, remove dead copper, pour order 623): -56.525,352.8
AGND on Bottom Layer "Bottom Layer-AGND 5" (hatched Horizontal grid 0.2 track 0.2, remove dead copper, pour order 525): -57.225,335.825
no net on Signal Layer 2 "Signal Layer 2-No Net 1" (hatched Horizontal grid 0.2 track 0.2, remove dead copper, pour order 869): -18.3,336.925
AGND on Signal Layer 2 "Bottom Layer-No Net" (hatched 90Degree grid 0.2 track 0.2, remove dead copper, pour order 321): 59.55,81.8 85.25,81.8 95.3,81.8 95.3,74.4 95.3,49.4 93.3,49.4 55.4,49.4 55.4,74.4 55.4,81.8 59.55,81.8
no net on Signal Layer 2 "Signal Layer 2-AGND_P" (hatched Horizontal grid 0.2 track 0.2, remove dead copper, pour order 499): -75.575,331.399
no net on Signal Layer 2 "Signal Layer 2-AGND_P 2" (hatched Horizontal grid 0.2 track 0.2, remove dead copper, pour order 489): -57.725,320.475
AGND_AP on Signal Layer 1 "Bottom Layer-No Net" (hatched 90Degree grid 0.2 track 0.2, remove dead copper, pour order 325): 93.3,49.4 95.3,49.4 95.3,81.8 85.25,81.8 55.4,81.8 55.4,74.4 55.4,49.4 67.3,49.4

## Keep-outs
Top Layer:
  lines w0.1: 81.35,71.125 81.55,71.125
  lines w0.12: 67.3,49.4 cw(c67.3,51.4) 67.3,53.4 71.3,53.4 cw(c71.3,51.4) 71.3,49.4 ; 89.3,49.4 cw(c89.3,51.4) 89.3,53.4 93.3,53.4 cw(c93.3,51.4) 93.3,49.4
Signal Layer 2:
  lines w0.1: 68.55,77.825 68.55,70.62 70.57,68.6
Bottom Layer:
  circle w0.1: c76.625,71.825 r0.8
  circle w0.12: c67.3,51.4 r2
  circle w0.12: c93.3,51.4 r2
Keep-Out Layer:
  lines w0.15: 57.4,78.6 57.4,76.4 cw(c56.4,76.4) 56.4,75.4 ccw(c56.4,74.4) 55.4,74.4 55.4,55.1 ccw(c56.4,55.1) 56.4,54.1 63.3,54.1 cw(c63.3,52.1) 65.3,52.1 65.3,51.4 ccw(c67.3,51.4) 67.3,49.4 93.3,49.4 ccw(c93.3,51.4) 95.3,51.4 95.3,74.4 ccw(c94.3,74.4) 94.3,75.4 88.4,75.4 cw(c88.4,76.4) 87.4,76.4 87.4,78.6

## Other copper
Top Layer:
  rectangle net AGND_AP: 75.35,55.55 80.575,57.15
  rectangle net L+VCC: 89.05,69.05 90.45,71.6
  rectangle net L+VCC: 88.545,67.962 90.1,69.829
  rectangle net NetC20_1: 85.325,71.15 85.893,71.475
  rectangle net NetC20_2: 86.925,70.275 87.825,71.159
  rectangle net R+VCC: 72.025,69.9 73.113,71.225
  rectangle net AGND_AP: 74.428,67.15 75.45,67.875
  rectangle net AGND_AP: 75.825,71.115 76.257,71.825
  rectangle net R+VCC: 71.636,69.829 72.636,71.225
  rectangle net RI-: 62.5,72.696 63.4,73.55
  rectangle net RO+: 67.775,72.66 68.675,73.45
  rectangle net AMP_R+: 66.5,72.725 66.75,73.275
  rectangle net AMP_R+: 66.7,72.834 66.95,73.525
  rectangle net R+VCC: 72.025,69.05 72.925,69.9
  rectangle net R+VCC: 71.232,68.1 72.925,69.7
  rectangle net R-VEE: 59.825,77.65 61,81.55
  rectangle net R+VCC: 65.8,77.55 66.6,79
  rectangle net R-VEE: 61,78.225 61.8,79
  rectangle net RI-: 73.1,78.5 73.25,78.75
  rectangle net RI-: 73.075,78.65 73.525,78.9
  rectangle net RO-: 71.825,78.175 72.025,78.5
  rectangle net RO-: 71.475,77.95 71.825,78.5
  rectangle net RO-: 71.375,78.4 72.2,78.9
  rectangle net RO-: 59.125,72.375 59.975,73.075
  rectangle net RI+: 81.6,78.05 81.8,78.125
  rectangle net RI+: 81.2,77.7 81.6,78.125
  rectangle net RI+: 80.9,77.6 81.3,78.2
  rectangle net RI+: 81,78.075 81.775,78.925
  rectangle net RO+: 82.6,78.275 83.325,78.95
Bottom Layer:
  rectangle net L-VEE: 60.6,77.178 61.4,78.181
  rectangle net L-VEE: 59.85,77.15 60.625,81.55
  rectangle net L-VEE: 60.6,77.8 61.4,79.2
  rectangle net L+VCC: 65.4,76.375 66.2,79

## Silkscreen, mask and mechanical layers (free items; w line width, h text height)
Top Overlay:
  drawing of 538 lines, arcs and shapes, not listed
  text "XD-05 PRO OAMP" at 72.7,52.4 h2
  text "20230518_V1.7" at 75.4,50.8 h1.5
Bottom Overlay:
  drawing of 538 lines, arcs and shapes, not listed
  text "XD-05 PRO OAMP" at 87.9,52.4 h2
  text "20230518_V1.7" at 85.2,50.8 h1.5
